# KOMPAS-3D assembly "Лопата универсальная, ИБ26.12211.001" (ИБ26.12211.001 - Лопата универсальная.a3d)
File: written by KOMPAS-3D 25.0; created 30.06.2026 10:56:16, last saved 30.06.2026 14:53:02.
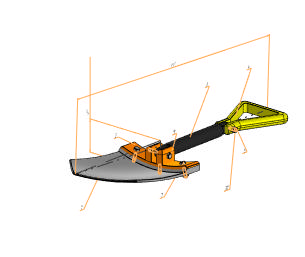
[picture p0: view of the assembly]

Document properties: Автор: Админ; Полное имя файла: C:\Users\Админ\Desktop\Лопата\Лопата\КОМПАС\ИБ26.12211.001 - Лопата универсальная.a3d; Организация: Алмаз-Антей Инженеры будушего 2026

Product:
- Part/product: Лопата универсальная  | designation ИБ26.12211.001
    Масса: 1.778971
    Форматы листов документа: A4
    signatures: Проверил Чернядьева О.Я.; Разработал Андреасян О.Г.
    source file: ИБ26.12211.001 - Лопата универсальная.spw
  - Component [detail]: Совок  | designation ОВСП.000000.001  | qty 1  | pos. 1  | Масса: 0.832152; Автор: user1; source file: ОВСП.000000.001 - Совок.m3d
  - Component [detail]: Основание  | designation ОВСП.000001.001  | qty 1  | pos. 2  | Масса: 0.267645; Автор: Админ; source file: ..\..\..\..\Documents\ОВСП.000001.001 - Основание.m3d
  - Component [detail]: Черенок  | designation ОВСП.000001.002  | qty 1  | pos. 3  | Масса: 0.34716; Автор: Админ; source file: ..\..\..\..\Documents\ОВСП.000001.002 - Черенок.m3d
  - Component [detail]: Ручка  | designation ОВСП.000001.003  | qty 1  | pos. 4  | Масса: 0.296175; Автор: Админ; source file: ..\..\..\..\Documents\ОВСП.000001.003 - Ручка.m3d
  - Component [standard]: Болт М5-6gx40 ГОСТ 7805-70  | qty 1  | pos. 9  | Масса: 0.007456; Раздел спецификации: Стандартные изделия; Рассекать на разрезах: no
  - Component [standard]: Гайка М5-6H ГОСТ 5915-70  | qty 5  | pos. 10  | Масса: 0.00144; Раздел спецификации: Стандартные изделия; Рассекать на разрезах: no
  - Component [standard]: Болт М5-6gx22 ГОСТ 7805-70  | qty 3  | pos. 7  | Масса: 0.004679; Раздел спецификации: Стандартные изделия; Рассекать на разрезах: no
  - Component [standard]: Болт М5-6gx38 ГОСТ 7805-70  | qty 1  | pos. 8  | Масса: 0.007147; Раздел спецификации: Стандартные изделия; Рассекать на разрезах: no
- Part/product: Лопата универсальная  | designation ИБ26.12211.001
    Масса: 1.778971
    Форматы листов документа: A4
    Вариант: Вид в сборе
    signatures: Проверил Чернядьева О.Я.; Разработал Андреасян О.Г.
    source file: ИБ26.12211.001 - Лопата универсальная.spw
  - Component [detail]: Совок  | designation ОВСП.000000.001  | qty 1  | pos. 1  | Масса: 0.832152; Автор: user1; source file: ОВСП.000000.001 - Совок.m3d
  - Component [detail]: Основание  | designation ОВСП.000001.001  | qty 1  | pos. 2  | Масса: 0.267645; Автор: Админ; source file: ..\..\..\..\Documents\ОВСП.000001.001 - Основание.m3d
  - Component [detail]: Черенок  | designation ОВСП.000001.002  | qty 1  | pos. 3  | Масса: 0.34716; Автор: Админ; source file: ..\..\..\..\Documents\ОВСП.000001.002 - Черенок.m3d
  - Component [detail]: Ручка  | designation ОВСП.000001.003  | qty 1  | pos. 4  | Масса: 0.296175; Автор: Админ; source file: ..\..\..\..\Documents\ОВСП.000001.003 - Ручка.m3d
  - Component [standard]: Болт М5-6gx40 ГОСТ 7805-70  | qty 1  | pos. 9  | Масса: 0.007456; Раздел спецификации: Стандартные изделия; Рассекать на разрезах: no
  - Component [standard]: Гайка М5-6H ГОСТ 5915-70  | qty 5  | pos. 10  | Масса: 0.00144; Раздел спецификации: Стандартные изделия; Рассекать на разрезах: no
  - Component [standard]: Болт М5-6gx22 ГОСТ 7805-70  | qty 3  | pos. 7  | Масса: 0.004679; Раздел спецификации: Стандартные изделия; Рассекать на разрезах: no
  - Component [standard]: Болт М5-6gx38 ГОСТ 7805-70  | qty 1  | pos. 8  | Масса: 0.007147; Раздел спецификации: Стандартные изделия; Рассекать на разрезах: no

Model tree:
1. Технические требования  (with: Сечение модели:1)  (labels: Затяжку резьбовых соединений производить по ГОСТ 1759.4-87.; ИБ26.12211.001)
2. Контекстная связь:2  (with: Смещенная плоскость:1, Контекстная связь (ОВСП.000001.001 Основание):2)
3. Контекстная связь:3  (with: Эскиз:1, Контекстная связь (ОВСП.000001.001 Основание):3)
4. Контекстная связь:10  (with: Эскиз:6, Контекстная связь (ОВСП.000001.001 Основание):10)
5. Контекстная связь:11  (with: Контекстная связь (ОВСП.000001.001 Основание):11)
6. Контекстная связь:12  (with: Смещенная плоскость:2, Контекстная связь (ОВСП.000001.001 Основание):12)
7. Контекстная связь:13  (with: Эскиз:7, Ребро. Фаска:1, Контекстная связь (ОВСП.000001.001 Основание):13)
8. Контекстная связь:14  (with: Контекстная связь (ОВСП.000001.001 Основание):14)
9. Контекстная связь:15  (with: Эскиз:8, Контекстная связь (ОВСП.000001.001 Основание):15)
10. Линейный размер:1  (with: Ребро.Фаска:3, Вершина.Скругление:1)
     Значение = 452.545
11. Линейный размер:2  (with: Вершина. Фаска:2, Ребро.Фаска:3)
     Значение = 55.3324
12. Обозначение позиции:1  (with: Грань.Элемент по траектории:2)  (labels: 3002089644 |; instProperty3D)
13. Обозначение позиции:2  (with: Грань.Элемент вращения:1)  (labels: 886537713 |; instProperty3D)
14. Обозначение позиции:3  (with: Грань.Элемент выдавливания:2)  (labels: 434913353 |; instProperty3D)
15. Обозначение позиции:4  (with: Грань.Элемент выдавливания:2)  (labels: 2299359376 |; instProperty3D)
16. Обозначение позиции:5  (with: Ребро. Фаска наружная:2)  (labels: 1435293258 |; instProperty3D)
17. Обозначение позиции:6  (labels: 2726337106 |; instProperty3D)
18. Обозначение позиции:7  (with: Ребро. Фаска:1)  (labels: 860075298 |; instProperty3D)
19. Обозначение позиции:8  (with: Грань.Элемент выдавливания:2, Грань.Элемент выдавливания:1, Грань.Элемент выдавливания:3, Ребро. Фаска:4, Ребро. Фаска:2, Грань.Элемент выдавливания:4)  (labels: 2673285486 |; instProperty3D; Грань.Элемент выдавливания:1.Экземпляр ( 2 ); Грань.Элемент выдавливания:3.Экземпляр ( 2 ))
     Ориентация = 2

Referenced files in C:\Users\Админ\Desktop\Лопата\Лопата\КОМПАС\: ОВСП.000000.001 - Совок.m3d
Referenced files in C:\Users\Админ\Documents\: ОВСП.000001.001 - Основание.m3d, ОВСП.000001.002 - Черенок.m3d, ОВСП.000001.003 - Ручка.m3d
Referenced files in C:\Program Files\ASCON\KOMPAS-3D v24\Libs\PolynomLib\DATA\vault\Methods\Kompas\3D\: PLib_Bolt_1_900.m3d, PLib_Nut_OST92_900.m3d
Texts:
  ОВСП.000000.001
  ОВСП.000001.001
  ОВСП.000001.002
  ОВСП.000001.003
  Крепежное изделие ГОСТ
  BOSimple***PART:6c77ca92-b8f2-c5f3-abdb-d99ba1e2418f***SHORTLOC:Root±30±20±10±80±10±©{}30±©{BASE}130±30[Нет;Без покрытия;Без указания материала;40;5;8;0,8;-]
  BOSimple***PART:0338bb82-6b79-df62-da33-8b23172f1b3e***SHORTLOC:Root±30±10±20±©{}110±10±50±60[Нет;Без покрытия;Без указания материала;-;5;0,8;8]
  BOSimple***PART:e3774f5e-c650-0458-95a9-8cc05c2ca4c2***SHORTLOC:Root±30±20±10±80±10±©{}30±©{BASE}130±30[Нет;Без покрытия;Без указания материала;22;5;8;0,8;-]
  BOSimple***PART:edf27907-1e24-e01a-2d8b-9814eb98b3f4***SHORTLOC:Root±30±20±10±80±10±©{}30±©{BASE}130±30[Нет;Без покрытия;Без указания материала;38;5;8;0,8;-]
  Программные изделия  и базы данных
  * Размеры для справок.
  Острые кромки притупить.
  Неуказанные предельные отклонения размеров: H14, h14, ±IT14/2.
  Маркировать обозначение и клеймить ОТК на бирке.
  Точка начала. Х
  Точка начала. Y
  Точка начала. Z
  ОВСП.000000.001 Совок
  ОВСП.000001.001 Основание
  ОВСП.000001.002 Черенок
  ОВСП.000001.003 Ручка
  hole1
  hole2
  Гайка М5-6H ГОСТ 5915-70 (1)
  bcut1
  hcut1
  cut1
  Болт М5-6gx22 ГОСТ 7805-70 (1)
  Болт М5-6gx22 ГОСТ 7805-70 (2)
  Болт М5-6gx22 ГОСТ 7805-70 (3)
  Гайка М5-6H ГОСТ 5915-70 (2)
  Гайка М5-6H ГОСТ 5915-70 (3)
  Гайка М5-6H ГОСТ 5915-70 (4)
  Гайка М5-6H ГОСТ 5915-70 (5)
  Грань. Головка шестигранная
  Грань.Элемент выдавливания:5.Экземпляр ( 2 )

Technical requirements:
  * Размеры для справок.
  GOST Type AU
  Затяжку резьбовых соединений производить по ГОСТ 1759.4-87.
  Острые кромки притупить.
  Неуказанные предельные отклонения размеров: H14, h14, ±IT14/2.
  Маркировать обозначение и клеймить ОТК на бирке.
